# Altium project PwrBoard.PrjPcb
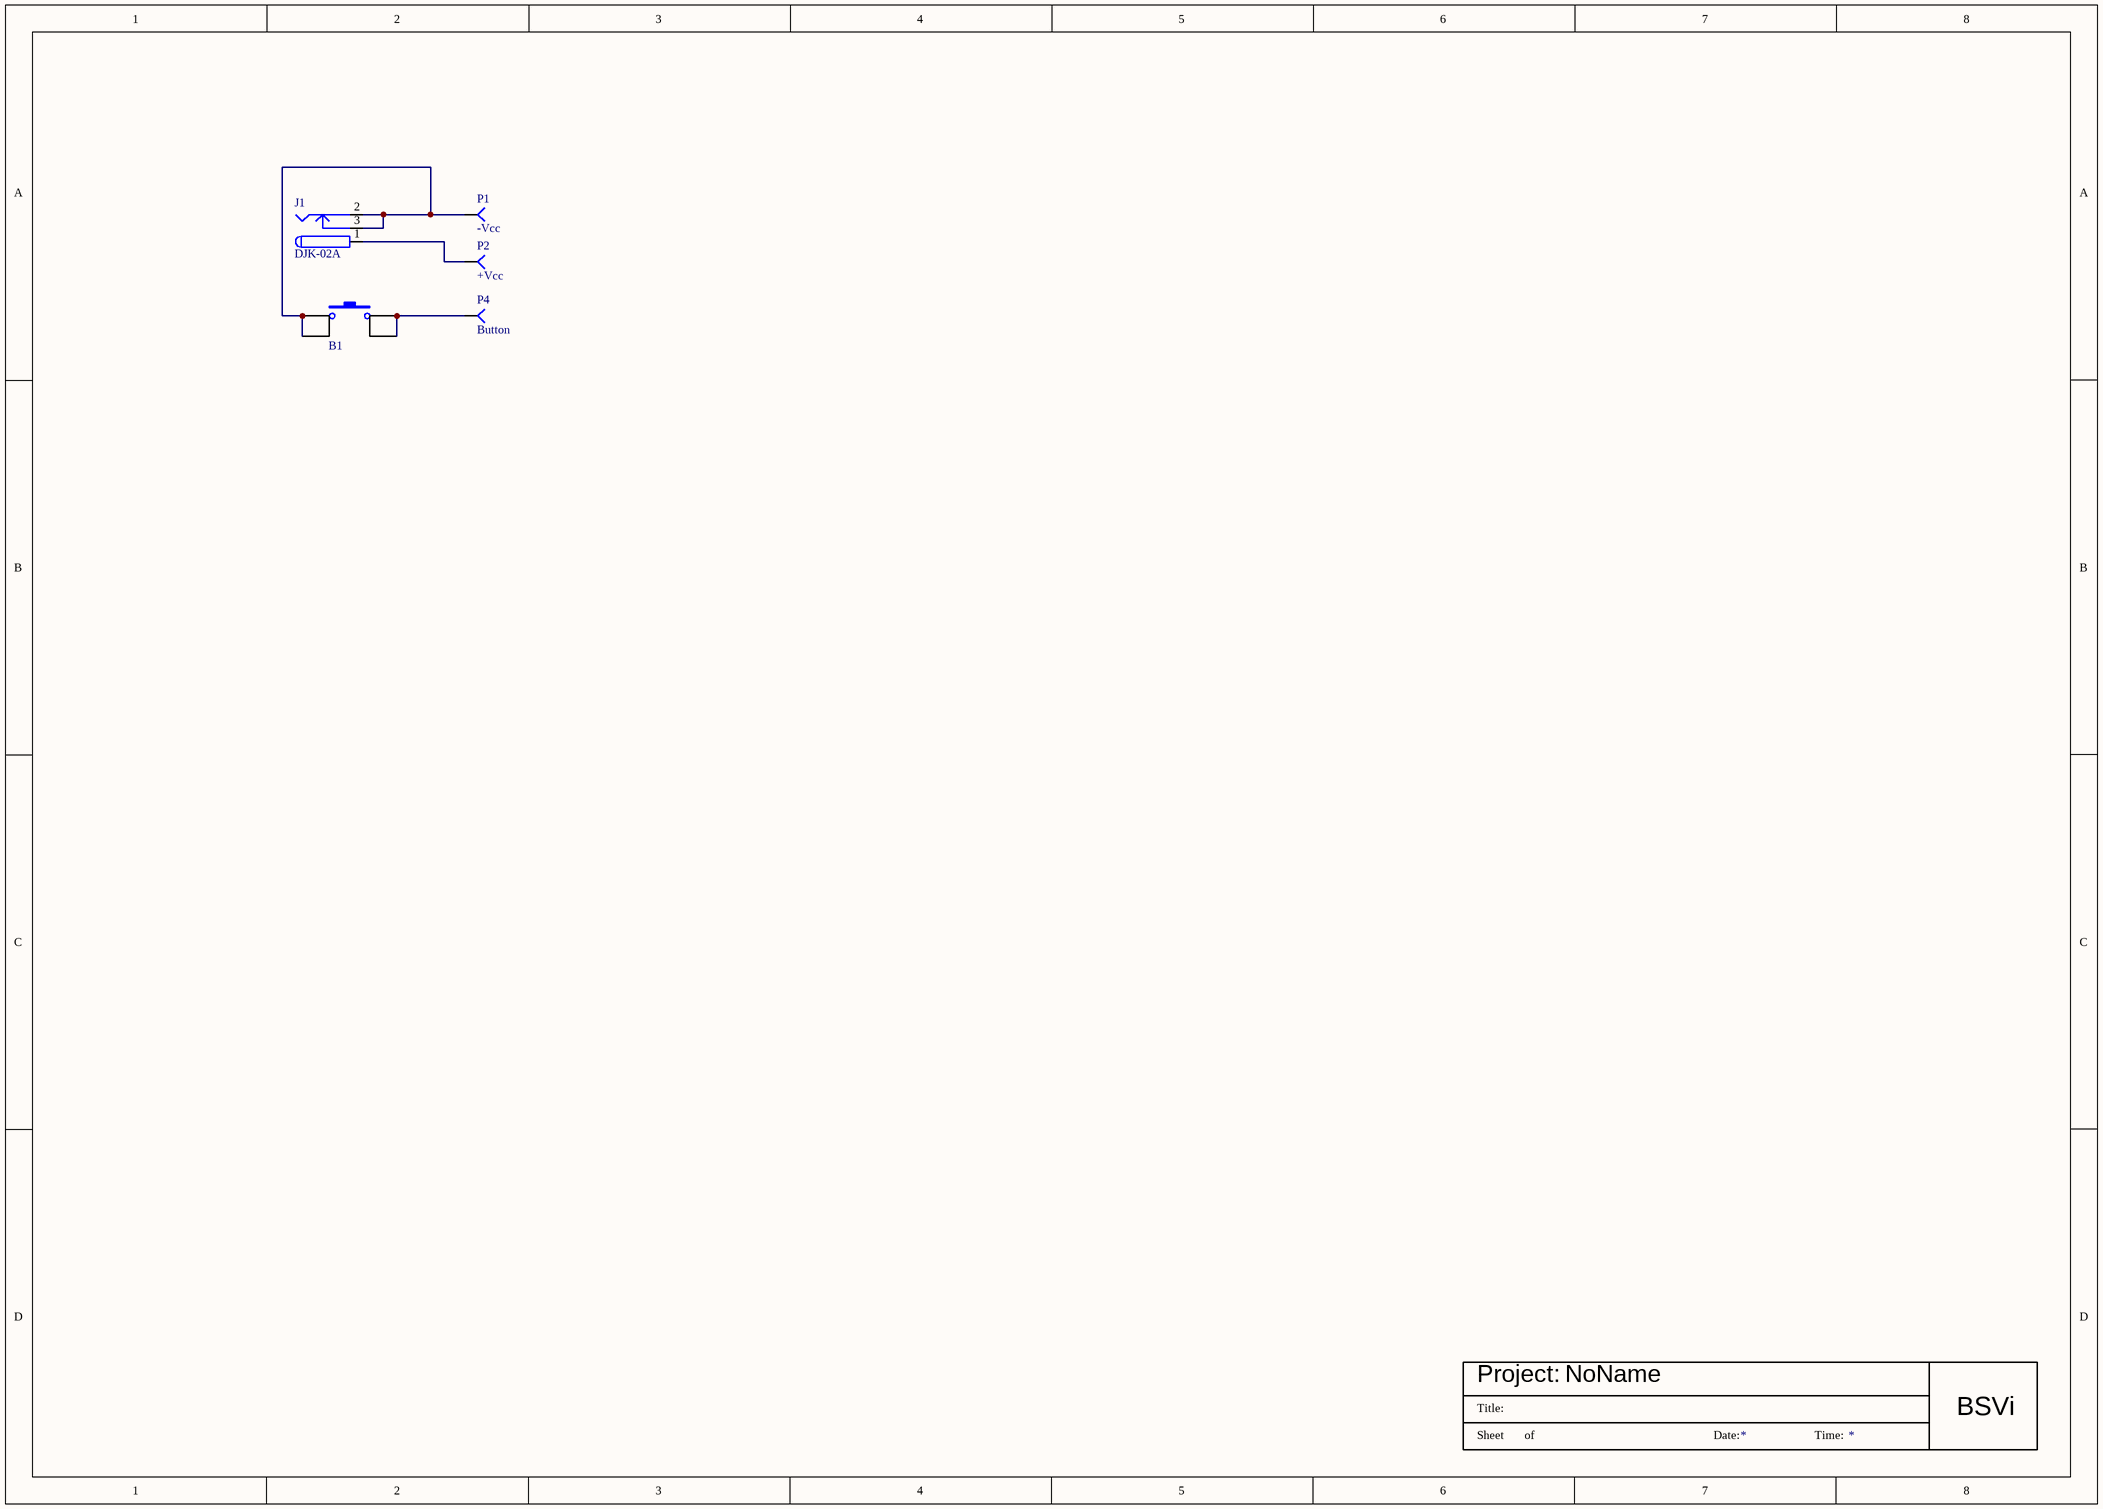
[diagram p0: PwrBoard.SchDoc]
1 sheet, 5 parts. Net scope: global (net labels, ports and power ports of the same name join across sheets).
Board file: PwrBoard.PcbDoc

## Sheet PwrBoard.SchDoc
size A3

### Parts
B1  BUTTON  [BUTTON]  (value not drawn)
J1  DJK-02A  [DJK-02A]
P1  -Vcc  [Pin 2.0x0.5]  (no BOM)
P2  +Vcc  [Pin 2.0x0.5]  (no BOM)
P4  Button  [Pin 2.0x0.5]  (no BOM)

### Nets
NetB1_1: B1.1 B1.2 J1.2 J1.3 P1.1
NetB1_3: B1.3 B1.4 P4.1
NetJ1_1: J1.1 P2.1

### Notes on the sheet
- Project:
- Title:
- Sheet
- of
- Date:
- Time:
- BSVi

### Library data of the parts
B1 = BUTTON_TACT
J1 = DJK-02A: Low Voltage Power Supply Connector
P1 P2 P4 = Pin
